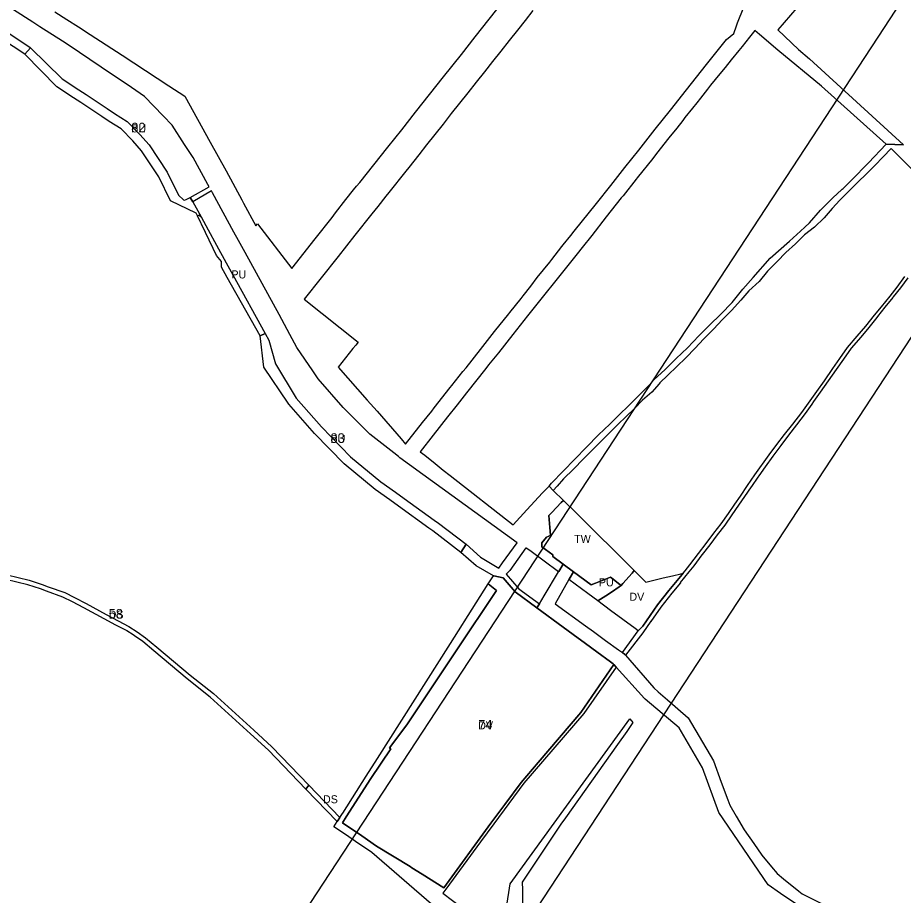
# Model space of a CAD drawing. Extents: x -537034 to -534353, y -1176562 to -1173176.
# Drawn here: x -535838 to -535284, y -1176098 to -1175550 of the extents above; entities that cross this region are included whole.
import ezdxf

# ---------------------------------------------------------------- set-up
doc = ezdxf.new("R2010")
doc.units = 0
for name, color, linetype in [('90320013', 7, 'Continuous'), ('90320023', 7, 'Continuous'), ('90350013', 7, 'Continuous'), ('90350023', 7, 'Continuous'), ('90350033', 7, 'Continuous'), ('90390013', 7, 'Continuous'), ('90390023', 7, 'Continuous'), ('90450013', 7, 'Continuous'), ('90450023', 7, 'Continuous'), ('ID_navrh', 7, 'Continuous')]:
    doc.layers.add(name, color=color, linetype=linetype)

msp = doc.modelspace()

# ---------------------------------------------------------------- linework, layer by layer
at = {"layer": '90320013'}
for points in [[(-535277.83, -1175645.64), (-535292.07, -1175631.59), (-535297.1, -1175636.81), (-535302.18, -1175642.08), (-535303.45, -1175643.39), (-535307.45, -1175647.28), (-535312.98, -1175652.65), (-535318.28, -1175657.99), (-535324.03, -1175663.79), (-535328.88, -1175668.99), (-535334, -1175674.87), (-535339.91, -1175680.56), (-535346.28, -1175685.46), (-535351.9, -1175691.02), (-535357.8, -1175696.49), (-535363.35, -1175702.16), (-535369.31, -1175708.05), (-535374.5, -1175714.58), (-535380.94, -1175720.41), (-535385.87, -1175726.27), (-535391.82, -1175732.67), (-535397.45, -1175738.23), (-535403.08, -1175744.29), (-535409.2, -1175750.56), (-535414.56, -1175756.25), (-535420.37, -1175762.32), (-535425.89, -1175767.64), (-535431.5, -1175773.03), (-535436.58, -1175777.9), (-535436.99, -1175778.38), (-535441.52, -1175783.7), (-535447.3, -1175788.74), (-535452.46, -1175793.8), (-535457.48, -1175798.84), (-535462.75, -1175803.92), (-535467.8, -1175808.78), (-535473.11, -1175814.36), (-535478.19, -1175819.27), (-535478.81, -1175819.87), (-535484.32, -1175825.2), (-535490.55, -1175831.73), (-535496.67, -1175837.74), (-535500.71, -1175842.26), (-535503.12, -1175844.96), (-535505.73, -1175842.26), (-535504.12, -1175840.57), (-535496.82, -1175832.93), (-535482.44, -1175818.09), (-535474.86, -1175810.24), (-535467.82, -1175803.62), (-535464.16, -1175800.19), (-535453.61, -1175789.75), (-535443.22, -1175779.35), (-535440.02, -1175775.76), (-535433.53, -1175769.76), (-535426.29, -1175762.73), (-535419.26, -1175755.91), (-535412.29, -1175748.56), (-535405.44, -1175741.83), (-535398.42, -1175734.92), (-535391.39, -1175727.68), (-535384.7, -1175719.38), (-535378.22, -1175712.03), (-535367.67, -1175699.94), (-535355.61, -1175689.31), (-535348.76, -1175683.14), (-535345.98, -1175680.56), (-535343.16, -1175677.96), (-535336.29, -1175670.08), (-535336.04, -1175669.84), (-535328.93, -1175662.85), (-535328.49, -1175662.42), (-535322.82, -1175657.13), (-535322.65, -1175656.98), (-535322.11, -1175656.46), (-535316.75, -1175651.25), (-535306.21, -1175640.54), (-535295.21, -1175628.81), (-535284.44, -1175629.29)], [(-535281.64, -1175712.35), (-535286.29, -1175718.5), (-535290.74, -1175724.1), (-535291.03, -1175724.47), (-535295.93, -1175730.65), (-535300.55, -1175736.46), (-535301.07, -1175737.11), (-535306.01, -1175743.34), (-535311.1, -1175749.33), (-535317.02, -1175756.28), (-535321.9, -1175763.11), (-535326.37, -1175769.45), (-535331.39, -1175776.57), (-535336.42, -1175783.7), (-535340.52, -1175789.52), (-535341.62, -1175791.07), (-535345.85, -1175797.07), (-535351.21, -1175804.11), (-535356.16, -1175810.6), (-535360.98, -1175816.94), (-535366.06, -1175823.6), (-535370.76, -1175830.27), (-535374.77, -1175835.95), (-535375.28, -1175836.68), (-535379.37, -1175842.48), (-535379.57, -1175842.76), (-535383.68, -1175848.73), (-535387.49, -1175854.29), (-535391.55, -1175860.18), (-535395.99, -1175866.64), (-535400.66, -1175872.73), (-535405.39, -1175878.91), (-535410.04, -1175884.99), (-535410.29, -1175885.31), (-535415.4, -1175891.99), (-535416.43, -1175893.34), (-535418.41, -1175895.85), (-535423.87, -1175902.55), (-535423.74, -1175902.66), (-535423.68, -1175902.65), (-535429.03, -1175909.14), (-535435.91, -1175917.94), (-535442.12, -1175926.9), (-535442.17, -1175926.57), (-535447.21, -1175933.95), (-535457.98, -1175947.84), (-535458.33, -1175947.43), (-535459.92, -1175946.27), (-535450.09, -1175932.67), (-535448.67, -1175931.14), (-535447.13, -1175929.73), (-535437.92, -1175916.46), (-535430.98, -1175907.57), (-535422.66, -1175897.47), (-535422.03, -1175896.71), (-535420.76, -1175895.17), (-535417.77, -1175891.54), (-535412.35, -1175884.45), (-535407.69, -1175878.19), (-535402.84, -1175871.73), (-535398.2, -1175865.9), (-535393.74, -1175859.47), (-535389.71, -1175853.51), (-535386.27, -1175848.61), (-535381.9, -1175841.97), (-535377.28, -1175835.27), (-535368.22, -1175822.74), (-535363.4, -1175816.29), (-535358.7, -1175810.03), (-535353.58, -1175803.58), (-535347.76, -1175796.36), (-535342.64, -1175789.05), (-535338.4, -1175783.34), (-535333.76, -1175776.49), (-535328.58, -1175768.96), (-535324.06, -1175762.7), (-535319.4, -1175755.73), (-535313.4, -1175748.77), (-535307.98, -1175742.53), (-535302.47, -1175735.7), (-535298.03, -1175730.3), (-535292.71, -1175723.69), (-535288.41, -1175718.1), (-535283.55, -1175711.47)], [(-535579.07, -1176103.38), (-535616.5, -1176070.96), (-535622.89, -1176066.65), (-535624.54, -1176065.54), (-535632.96, -1176059.86), (-535640.1, -1176055.04), (-535637.99, -1176051.72), (-535637.47, -1176050.91), (-535636.33, -1176049.12), (-535634.82, -1176046.75), (-535634.67, -1176046.52), (-535634.6, -1176046.41), (-535619.96, -1176023.48), (-535612.97, -1176012.45), (-535567.39, -1175940.55), (-535551.3, -1175915.16), (-535543.85, -1175903.41), (-535538.46, -1175907.57), (-535563.27, -1175944.59), (-535594.65, -1175991.42), (-535605.36, -1176005.77), (-535604.62, -1176006.3), (-535617.03, -1176024.82), (-535632.36, -1176048.86), (-535634.73, -1176052.58), (-535622.74, -1176060.73), (-535613.52, -1176066.99), (-535592.48, -1176079.84), (-535591.35, -1176080.53), (-535584.91, -1176084.6), (-535571.42, -1176093.12), (-535542.01, -1176052.66), (-535533.43, -1176041.1), (-535523.23, -1176027.37), (-535512.53, -1176014.91), (-535485.92, -1175983.59), (-535465.28, -1175953.69), (-535463.75, -1175955.3), (-535483.92, -1175984.25), (-535521.49, -1176027.83), (-535540.25, -1176053.13), (-535548.55, -1176064.33), (-535570.1, -1176093.95), (-535572.04, -1176096.44), (-535547.96, -1176114.72)], [(-535532.28, -1176105.42), (-535530.06, -1176090.53), (-535455.23, -1175987.51), (-535453.36, -1175989.8), (-535455.51, -1175993.05), (-535457.15, -1175995.54), (-535462.94, -1176003.66), (-535495.52, -1176049.34), (-535498.36, -1176053.32), (-535522.46, -1176089.49), (-535522.4, -1176094.37), (-535522.26, -1176104.52)]]:
    msp.add_lwpolyline(points, dxfattribs=at)
msp.add_lwpolyline([(-535636.33, -1176049.12), (-535637.47, -1176050.91), (-535637.99, -1176051.72), (-535657.54, -1176031.49), (-535655.86, -1176028.92)], close=True, dxfattribs=at)
at = {"layer": '90320023'}
msp.add_lwpolyline([(-535851.29, -1175896.02), (-535830.38, -1175901.03), (-535822.37, -1175903.66), (-535818.62, -1175905.16), (-535808.23, -1175908.79), (-535802.09, -1175911.79), (-535794.89, -1175915.67), (-535782.25, -1175922.56), (-535774.87, -1175926.44), (-535768.11, -1175929.95), (-535762.97, -1175933.33), (-535757.72, -1175936.96), (-535750.71, -1175942.84), (-535729.93, -1175960.24), (-535715.4, -1175971.76), (-535690.12, -1175994.66), (-535678.91, -1176005.05), (-535655.86, -1176028.92), (-535657.54, -1176031.49), (-535681.02, -1176007.2), (-535692.15, -1175996.87), (-535717.35, -1175974.04), (-535731.82, -1175962.56), (-535752.63, -1175945.14), (-535759.54, -1175939.34), (-535764.65, -1175935.81), (-535765.54, -1175935.22), (-535769.33, -1175932.73), (-535769.62, -1175932.54), (-535776.25, -1175929.1), (-535783.67, -1175925.2), (-535796.32, -1175918.31), (-535803.46, -1175914.46), (-535809.38, -1175911.56), (-535819.67, -1175907.97), (-535823.4, -1175906.48), (-535831.2, -1175903.92), (-535852.06, -1175898.92)], dxfattribs=at)
at = {"layer": '90350013'}
msp.add_lwpolyline([(-535450.09, -1175932.67), (-535451.97, -1175931.28), (-535459.65, -1175925.59), (-535467.29, -1175919.94), (-535475.36, -1175913.97), (-535470.3, -1175910.82), (-535466.66, -1175908.55), (-535461.94, -1175905.12), (-535460.77, -1175904.27), (-535459.69, -1175903.06), (-535453.93, -1175896.58), (-535452.5, -1175895.1), (-535445.31, -1175902.23), (-535434.4, -1175899.64), (-535428.55, -1175898.25), (-535423.33, -1175897.02), (-535422.03, -1175896.71), (-535422.66, -1175897.47), (-535430.98, -1175907.57), (-535437.92, -1175916.46), (-535447.13, -1175929.73), (-535448.67, -1175931.14)], close=True, dxfattribs=at)
at = {"layer": '90350023'}
msp.add_lwpolyline([(-535540.36, -1175898.34), (-535540.29, -1175898.38), (-535534.34, -1175899.65), (-535526.89, -1175908.36), (-535513.42, -1175918.29), (-535497.01, -1175930.38), (-535490.65, -1175935.04), (-535482.99, -1175940.63), (-535475.88, -1175945.79), (-535467.26, -1175952.11), (-535465.65, -1175953.29), (-535465.28, -1175953.69), (-535485.92, -1175983.59), (-535512.53, -1176014.91), (-535523.23, -1176027.37), (-535533.43, -1176041.1), (-535542.01, -1176052.66), (-535571.42, -1176093.12), (-535584.91, -1176084.6), (-535591.35, -1176080.53), (-535592.48, -1176079.84), (-535613.52, -1176066.99), (-535622.74, -1176060.73), (-535634.73, -1176052.58), (-535632.36, -1176048.86), (-535617.03, -1176024.82), (-535604.62, -1176006.3), (-535605.36, -1176005.77), (-535594.65, -1175991.42), (-535563.27, -1175944.59), (-535538.46, -1175907.57), (-535543.85, -1175903.41)], close=True, dxfattribs=at)
at = {"layer": '90350033'}
msp.add_lwpolyline([(-535199.83, -1175627.8), (-535772.63, -1176500.85), (-535775.96, -1176496.83), (-535783.4, -1176487.84), (-535787.33, -1176483.09), (-535803.54, -1176468.74), (-535807.04, -1176473.64), (-535813.34, -1176482.47), (-535818.56, -1176477.96), (-535831.94, -1176466.46), (-535834.68, -1176464.1), (-535838.2, -1176461.07), (-535839.73, -1176459.91), (-535842.84, -1176457.56), (-535842.29, -1176449.79), (-535843.77, -1176447.3), (-535846.01, -1176444.91), (-535855.86, -1176434.39), (-535854.45, -1176432.58), (-535865.15, -1176423.1), (-535300.19, -1175562.02), (-535233.47, -1175460.12)], dxfattribs=at)
at = {"layer": '90390013'}
msp.add_lwpolyline([(-535488.9, -1175859.05), (-535452.5, -1175895.1), (-535453.93, -1175896.58), (-535459.69, -1175903.06), (-535460.77, -1175904.27), (-535461.54, -1175903.7), (-535466.56, -1175899.68), (-535467.39, -1175899.1), (-535476.73, -1175902.94), (-535479.39, -1175904.03), (-535490.38, -1175895.82), (-535496.82, -1175891.01), (-535503.28, -1175886.18), (-535503.39, -1175885.12), (-535510.21, -1175880.2), (-535510.16, -1175877.77), (-535507.33, -1175874.25), (-535506.38, -1175873.74), (-535504.8, -1175872.9), (-535505.23, -1175868.24), (-535505.8, -1175860.7), (-535504.06, -1175858.87), (-535498.13, -1175852.62), (-535496.81, -1175851.22)], close=True, dxfattribs=at)
at = {"layer": '90390023'}
msp.add_lwpolyline([(-535337.12, -1176112.77), (-535361.09, -1176096.62), (-535368.9, -1176091.15), (-535399.63, -1176045.97), (-535409.82, -1176018.17), (-535424.54, -1175993.21), (-535445.68, -1175975.28), (-535446.09, -1175974.93), (-535463.75, -1175955.3), (-535465.28, -1175953.69), (-535465.65, -1175953.29), (-535467.26, -1175952.11), (-535475.88, -1175945.79), (-535482.99, -1175940.63), (-535490.65, -1175935.04), (-535497.01, -1175930.38), (-535513.42, -1175918.29), (-535511.8, -1175915.76), (-535508.75, -1175910.71), (-535499.78, -1175895.9), (-535499.58, -1175895.57), (-535496.82, -1175891.01), (-535490.38, -1175895.82), (-535493.15, -1175900.4), (-535493.32, -1175900.68), (-535501.85, -1175915.74), (-535482.98, -1175929.48), (-535477.95, -1175933.14), (-535470.45, -1175938.6), (-535462.35, -1175944.51), (-535459.92, -1175946.27), (-535458.33, -1175947.43), (-535457.98, -1175947.84), (-535440.26, -1175968.33), (-535437.53, -1175970.72), (-535431.84, -1175975.7), (-535425.27, -1175981.45), (-535418.91, -1175987.01), (-535403.12, -1176013.79), (-535398.17, -1176027.18), (-535394.14, -1176038.1), (-535392.88, -1176041.53), (-535388.88, -1176048.37), (-535383.95, -1176056.8), (-535377.89, -1176065.42), (-535372.8, -1176072.73), (-535366.75, -1176079.98), (-535363.21, -1176084.23), (-535359.23, -1176087.47), (-535349.8, -1176095.16), (-535347.64, -1176096.92), (-535334.8, -1176103.36)], dxfattribs=at)
at = {"layer": '90450013'}
for points in [[(-535350.92, -1175543.64), (-535362.76, -1175557.46), (-535349.88, -1175569.66), (-535343.16, -1175575.62), (-535284.44, -1175629.29), (-535295.21, -1175628.81), (-535335.54, -1175592.69), (-535362.75, -1175570.17), (-535374.23, -1175560.37), (-535377.31, -1175557.89), (-535380.54, -1175562.01), (-535385.08, -1175567.81), (-535387.18, -1175570.39), (-535391.96, -1175576.27), (-535395.79, -1175580.98), (-535396.95, -1175582.4), (-535401.9, -1175588.49), (-535404.84, -1175592.11), (-535406.74, -1175594.51), (-535411.23, -1175600.18), (-535413.46, -1175602.99), (-535416.14, -1175606.37), (-535420.85, -1175612.3), (-535422.2, -1175613.99), (-535426.01, -1175618.78), (-535430.88, -1175624.91), (-535438.55, -1175634.63), (-535440.97, -1175637.7), (-535450.62, -1175649.93), (-535451.29, -1175650.78), (-535459.55, -1175661.07), (-535460.64, -1175662.42), (-535470.01, -1175674.15), (-535479.01, -1175685.92), (-535484.99, -1175693.35), (-535488.25, -1175697.39), (-535500.75, -1175712.91), (-535510.03, -1175724.59), (-535519.13, -1175736.05), (-535528.31, -1175747.61), (-535537.36, -1175759.04), (-535543.48, -1175766.68), (-535545.24, -1175768.88), (-535557.22, -1175784), (-535563.17, -1175791.59), (-535569.11, -1175799.17), (-535578.13, -1175810.51), (-535586.24, -1175820.82), (-535583.41, -1175823.06), (-535576.85, -1175828.25), (-535571.77, -1175832.29), (-535567.45, -1175835.71), (-535528.13, -1175866.54), (-535519.59, -1175857.1), (-535509.79, -1175846.51), (-535505.73, -1175842.26), (-535503.12, -1175844.96), (-535496.81, -1175851.22), (-535498.13, -1175852.62), (-535504.06, -1175858.87), (-535505.8, -1175860.7), (-535505.23, -1175868.24), (-535504.8, -1175872.9), (-535506.38, -1175873.74), (-535507.33, -1175874.25), (-535510.16, -1175877.77), (-535510.21, -1175880.2), (-535503.39, -1175885.12), (-535503.28, -1175886.18), (-535496.82, -1175891.01), (-535499.58, -1175895.57), (-535499.78, -1175895.9), (-535517.79, -1175882.58), (-535519.97, -1175880.97), (-535520.21, -1175880.83), (-535530.28, -1175894.97), (-535530.28, -1175894.98), (-535532.44, -1175897.3), (-535524.53, -1175906.37), (-535511.8, -1175915.76), (-535513.42, -1175918.29), (-535526.89, -1175908.36), (-535534.34, -1175899.65), (-535540.29, -1175898.38), (-535540.36, -1175898.34), (-535551.25, -1175892.1), (-535560.76, -1175883.69), (-535557.47, -1175878.66), (-535548.52, -1175886.64), (-535537, -1175893.45), (-535534.77, -1175890.22), (-535525.59, -1175877.78), (-535525.69, -1175877.72), (-535598.9, -1175824.62), (-535599.85, -1175823.87), (-535602.78, -1175821.58), (-535617.59, -1175809.94), (-535634.23, -1175793.2), (-535649.91, -1175775.29), (-535653.32, -1175770.27), (-535663.21, -1175755.7), (-535667.59, -1175747.69), (-535674.39, -1175735.25), (-535695.56, -1175696.43), (-535699.66, -1175689.03), (-535702.55, -1175683.75), (-535715.95, -1175659.24), (-535716.58, -1175658.08), (-535728.28, -1175664.92), (-535729.79, -1175662.18), (-535718.04, -1175655.42), (-535718.77, -1175654.08), (-535728.01, -1175637.17), (-535733.33, -1175628.97), (-535741.1, -1175617), (-535746.78, -1175611.09), (-535758.36, -1175599.06), (-535766.5, -1175593.57), (-535785.45, -1175580.79), (-535806.1, -1175566.86), (-535809.57, -1175564.63), (-535823.67, -1175555.59), (-535828.09, -1175552.76), (-535854.81, -1175535.62)], [(-535814.31, -1175546.18), (-535806.99, -1175550.94), (-535799.67, -1175555.68), (-535792.35, -1175560.43), (-535782.37, -1175566.9), (-535772.4, -1175573.37), (-535765.08, -1175578.12), (-535757.76, -1175582.87), (-535750.43, -1175587.62), (-535743.12, -1175592.37), (-535733.14, -1175598.84), (-535725.25, -1175613.24), (-535717.41, -1175627.58), (-535707.41, -1175645.42), (-535697.65, -1175663.55), (-535696.48, -1175665.72), (-535688.85, -1175679.9), (-535687.79, -1175678.56), (-535666.47, -1175706.55), (-535651.78, -1175688.01), (-535641.22, -1175674.69), (-535639.03, -1175671.66), (-535632.59, -1175663.38), (-535627.79, -1175657.46), (-535625.98, -1175655.06), (-535623.83, -1175652.75), (-535615.14, -1175641.77), (-535606.44, -1175630.8), (-535597.75, -1175619.83), (-535589.05, -1175608.86), (-535580.36, -1175597.89), (-535571.66, -1175586.91), (-535560.48, -1175572.81), (-535551.78, -1175561.84), (-535543.09, -1175550.86), (-535534.39, -1175539.89)], [(-535515.85, -1175545.46), (-535520.75, -1175551.69), (-535525.53, -1175557.72), (-535530.69, -1175564.23), (-535535.84, -1175570.73), (-535540.99, -1175577.24), (-535546.15, -1175583.74), (-535551.3, -1175590.24), (-535556.46, -1175596.75), (-535561.61, -1175603.25), (-535566.77, -1175609.76), (-535571.92, -1175616.26), (-535577.08, -1175622.77), (-535582.23, -1175629.27), (-535587.05, -1175635.46), (-535593.34, -1175643.37), (-535595.28, -1175645.72), (-535605.83, -1175659.04), (-535607.67, -1175661.34), (-535612.76, -1175667.75), (-535616.39, -1175672.37), (-535626.95, -1175685.69), (-535637.51, -1175699.01), (-535648.06, -1175712.33), (-535658.62, -1175725.65), (-535624.89, -1175752.38), (-535626.49, -1175754.32), (-535628.2, -1175756.39), (-535637.37, -1175768.15), (-535619.28, -1175788.62), (-535613.13, -1175795.59), (-535598.09, -1175812.9), (-535595.4, -1175816.1), (-535584.69, -1175802.54), (-535579.05, -1175795.48), (-535577.46, -1175793.47), (-535567.43, -1175780.76), (-535566.52, -1175779.61), (-535559.53, -1175770.83), (-535557.59, -1175768.39), (-535548.62, -1175757.13), (-535539.72, -1175745.82), (-535530.84, -1175734.72), (-535530.27, -1175734.01), (-535523.25, -1175725.15), (-535521.95, -1175723.51), (-535517.19, -1175717.4), (-535513.12, -1175712.17), (-535505.33, -1175702.44), (-535504.04, -1175700.82), (-535497.68, -1175692.7), (-535496.93, -1175691.74), (-535492.21, -1175685.91), (-535490.03, -1175683.21), (-535476.18, -1175665.83), (-535467.24, -1175654.63), (-535458.37, -1175643.45), (-535449.7, -1175632.54), (-535439.48, -1175619.54), (-535429.85, -1175607.57), (-535419.87, -1175594.93), (-535407.31, -1175579.18), (-535394.99, -1175563.41), (-535390.29, -1175559.76), (-535388.66, -1175555.02), (-535387.97, -1175553), (-535384.13, -1175543.23)], [(-535845.34, -1175558.14), (-535830.04, -1175568.35), (-535829.54, -1175568.69), (-535833.24, -1175572.63), (-535847.63, -1175563)]]:
    msp.add_lwpolyline(points, dxfattribs=at)
for points in [[(-535682.99, -1175747), (-535686.24, -1175748.4), (-535706.69, -1175712.09), (-535710.39, -1175705.55), (-535710.39, -1175702.15), (-535713.49, -1175698.34), (-535715.53, -1175694.02), (-535722.71, -1175678.89), (-535723.18, -1175677.9), (-535725.26, -1175673.52), (-535724.3, -1175673.08), (-535723.1, -1175674.31), (-535718.62, -1175682.43), (-535713.43, -1175691.84), (-535707.3, -1175702.86), (-535703.23, -1175710.32)], [(-535493.32, -1175900.68), (-535493.15, -1175900.4), (-535490.38, -1175895.82), (-535479.39, -1175904.03), (-535476.73, -1175902.94), (-535467.39, -1175899.1), (-535466.56, -1175899.68), (-535461.54, -1175903.7), (-535460.77, -1175904.27), (-535461.94, -1175905.12), (-535466.66, -1175908.55), (-535470.3, -1175910.82), (-535475.36, -1175913.97), (-535481.58, -1175909.37)]]:
    msp.add_lwpolyline(points, close=True, dxfattribs=at)
at = {"layer": '90450023'}
for points in [[(-535728.28, -1175664.92), (-535723.1, -1175674.31), (-535724.3, -1175673.08), (-535725.26, -1175673.52), (-535726.09, -1175671.93), (-535742.1, -1175664.25), (-535749.45, -1175649.25), (-535760.21, -1175633), (-535765.67, -1175626.82), (-535772.94, -1175619.38), (-535780.39, -1175614.7), (-535785.08, -1175611.55), (-535798.16, -1175602.89), (-535802.74, -1175599.87), (-535813.09, -1175593.02), (-535833.24, -1175572.63), (-535829.54, -1175568.69), (-535809.76, -1175588.03), (-535799.42, -1175594.86), (-535794.85, -1175597.89), (-535781.75, -1175606.56), (-535777.12, -1175609.67), (-535769.15, -1175614.68), (-535761.28, -1175622.73), (-535755.43, -1175629.34), (-535744.24, -1175646.27), (-535737.19, -1175660.63), (-535734.04, -1175663.61), (-535733.47, -1175663.8), (-535732.42, -1175663.48), (-535729.79, -1175662.18)], [(-535557.47, -1175878.66), (-535560.76, -1175883.69), (-535578.42, -1175870.31), (-535580.92, -1175868.49), (-535599.68, -1175854.9), (-535605.12, -1175850.96), (-535614.39, -1175844.44), (-535633.72, -1175828.36), (-535652.23, -1175809.44), (-535668.17, -1175791.26), (-535668.77, -1175790.56), (-535683.8, -1175768), (-535686.24, -1175748.4), (-535682.99, -1175747), (-535680.67, -1175751.2), (-535676.62, -1175766.04), (-535663.64, -1175787.32), (-535647.82, -1175805.36), (-535629.65, -1175823.94), (-535610.74, -1175839.67), (-535601.63, -1175846.07), (-535596.16, -1175850.04), (-535577.41, -1175863.63), (-535574.85, -1175865.48)]]:
    msp.add_lwpolyline(points, close=True, dxfattribs=at)

# ---------------------------------------------------------------- texts
at = {"layer": '90320013'}
msp.add_text('DS', height=5, rotation=0, dxfattribs=at).set_placement((-535646.94, -1176040.31))
at = {"layer": '90320023'}
msp.add_text('DS', height=5, rotation=360, dxfattribs=at).set_placement((-535780.78, -1175925.02))
at = {"layer": '90350013'}
msp.add_text('DV', height=5, rotation=360, dxfattribs=at).set_placement((-535455.57, -1175913.88))
at = {"layer": '90350023'}
msp.add_text('DV', height=5, rotation=0, dxfattribs=at).set_placement((-535550, -1175994.23))
at = {"layer": '90390013'}
msp.add_text('TW', height=5, rotation=0, dxfattribs=at).set_placement((-535490.08, -1175877.74))
at = {"layer": '90450013'}
msp.add_text('PU', height=5, dxfattribs=at).set_placement((-535704.13, -1175712.66))
msp.add_text('PU', height=5, rotation=360, dxfattribs=at).set_placement((-535474.63, -1175904.89))
at = {"layer": '90450023'}
for p in [(-535766.68, -1175621.5), (-535642.25, -1175815.34)]:
    msp.add_text('PU', height=5, rotation=360, dxfattribs=at).set_placement(p)
at = {"layer": 'ID_navrh'}
for s, rotation, p in [('82', 360, (-535766.68, -1175621.5)), ('83', 360, (-535642.25, -1175815.34)), ('58', 360, (-535780.78, -1175925.02)), ('74', 0, (-535550, -1175994.23))]:
    msp.add_text(s, height=6, rotation=rotation, dxfattribs=at).set_placement(p)

doc.saveas('drawing.dxf')
